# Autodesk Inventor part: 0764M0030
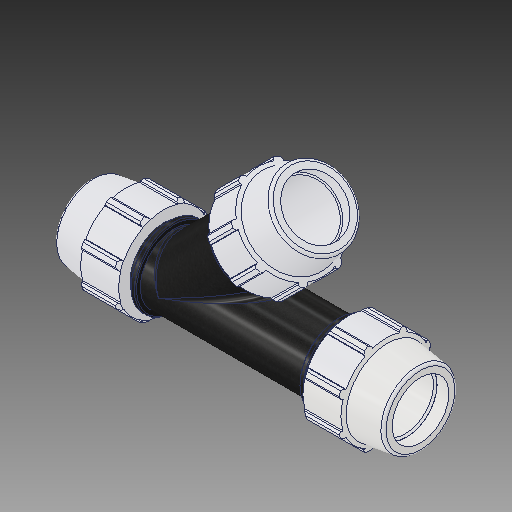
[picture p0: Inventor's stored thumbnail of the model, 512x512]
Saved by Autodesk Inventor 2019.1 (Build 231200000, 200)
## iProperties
Created: 2017-02
Part Number: 0764M0030
Material: PVC-Piping
Description: PLASSON 45° TEE 3'' - 3'' - 3''
Document SubType Name: Modeling
Designer: KIM
Mass: 92.6774 g
Surface Area: 199.44 cm^2
Volume: 66.1981 cm^3
Density: 1.4 g/cm^3
Appearance: PTFE
Author: Кирилл
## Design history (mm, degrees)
derived "0764M0.ipt"
feature "Solid1::0764M0.ipt"
feature "Solid3::0764M0.ipt"
tag "TaggingFeature1"
body "Solid1"
other parameters: "d2" = 88.7, "d4" = 21.42067, "d5" = 51.4096, "d7" = 151.892, "d11" = 8.56827, "d13" = 120 deg, "d14" = 115.31, "d15" = 8 deg, "d16" = 121.5136, "d18" = 4.435, "d19" = 35 deg, "d20" = 17.5 deg, "d21" = 141.25956, "d23" = 0, "d25" = 360 deg, "d27" = 3.03784, "d33" = 1.774, "d42" = 61.69152, "d43" = 4.55676, "d46" = 2.661, "d68" = 7.71144, "d91" = 106.3244, "d93" = 162.052, "d95" = 79.83, "d134" = 257.048, "d138" = 45 deg, "d141" = 232.918, "d144" = 0, "d146" = 0, "d150" = 4.435, "d158" = 8.87, "d165" = 356.5144, "d166" = 141.25956, "d167" = 35 deg, "d168" = 17.5 deg, "d170" = 0, "d172" = 360 deg, "d174" = 4.55676, "d177" = 3.03784, "d_" = 88.7, "E_" = 151.892, "A_" = 232.918, "l_" = 162.052, "H_" = 514.096
